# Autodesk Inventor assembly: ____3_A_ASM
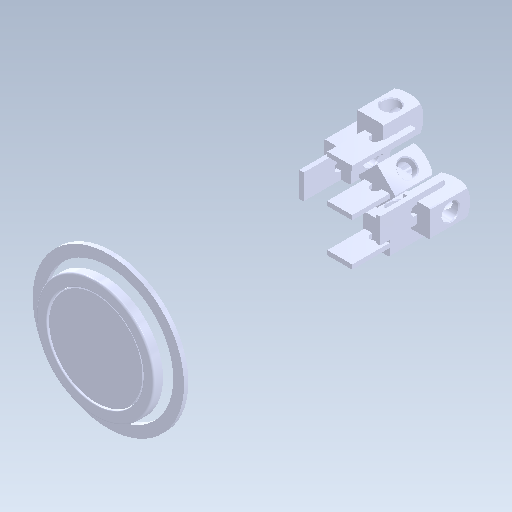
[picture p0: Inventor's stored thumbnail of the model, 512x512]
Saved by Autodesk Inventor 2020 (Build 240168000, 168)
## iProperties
Created: 2017-09
Part Number: ____3_A_ASM
Document SubType Name: Assembly
Designer: bruno
Sending System: SolidWorks 2016
Last Author: Prof
Last Saved: 2018-09-27
Author: bruno
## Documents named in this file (9)
- C:\Users\bruno\Documents\Systèmes\Mallette Bras robotisé (273265)\Dossier ressources\Maquette Dobot SW2016\____3_A_ASM.iam
- C:\Users\bruno\Documents\Systèmes\Mallette Bras robotisé (273265)\Dossier ressources\Maquette Dobot SW2016\BREP_1-935.ipt
- C:\Users\bruno\Documents\Systèmes\Mallette Bras robotisé (273265)\Dossier ressources\Maquette Dobot SW2016\BREP_2-936.ipt
- C:\Users\bruno\Documents\Systèmes\Mallette Bras robotisé (273265)\Dossier ressources\Maquette Dobot SW2016\BREP_3-937.ipt
- C:\Users\bruno\Documents\Systèmes\Mallette Bras robotisé (273265)\Dossier ressources\Maquette Dobot SW2016\BREP_4.ipt
- C:\Users\bruno\Documents\Systèmes\Mallette Bras robotisé (273265)\Dossier ressources\Maquette Dobot SW2016\BREP_5.ipt
- C:\Users\bruno\Documents\Systèmes\Mallette Bras robotisé (273265)\Dossier ressources\Maquette Dobot SW2016\BREP_6.ipt
- C:\Users\bruno\Documents\Systèmes\Mallette Bras robotisé (273265)\Dossier ressources\Maquette Dobot SW2016\BREP_7.ipt
- C:\Users\bruno\Documents\Systèmes\Mallette Bras robotisé (273265)\Dossier ressources\Maquette Dobot SW2016\BREP_8.ipt
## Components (8 placed, 8 different names)
1. BREP_1-935:1
2. BREP_2-936:1
3. BREP_3-937:1
4. BREP_4:1
5. BREP_5:1
6. BREP_6:1
7. BREP_7:1
8. BREP_8:1
